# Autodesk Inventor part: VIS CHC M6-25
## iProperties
Created: 2004-11
Part Number: VIS CHC M6-25
Document SubType Name: Modeling
Designer: Bruno
Manufacturer: Standard
Standards Organization: Custom
Author: Bruno
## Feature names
1. Base1
